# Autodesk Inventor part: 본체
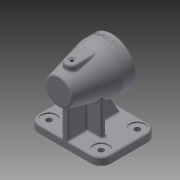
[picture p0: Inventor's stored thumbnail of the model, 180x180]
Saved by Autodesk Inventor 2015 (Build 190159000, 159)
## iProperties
Created: 2024-12
Part Number: 본체
Material: 일반
Document SubType Name: Modeling
Designer: 10401
Density: 1 g/cm^3
Appearance: 기본값
Author: 10401
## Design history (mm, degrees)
sketch "스케치1"
  geometry: L1 (-57, 44.5)-(57, 44.5); L2 (57, 44.5)-(57, -44.5); L3 (57, -44.5)-(-57, -44.5); L4 (-57, -44.5)-(-57, 44.5); L5 (-57, 44.5)-(57, -44.5); L6 (57, 44.5)-(-57, -44.5); 1 further point
  constraints: 12 end point, 2 midpoint, 2 parallel, 1 horizontal, 1 perpendicular
  dimensions: "d0" = 114 distance of L1.start L1.end; "d1" = 89 distance of L1.end L2.end
extrude "돌출1" new body sketch "스케치1" distance "d2" = 12; taper "d3" = 0 deg
fillet "모깎기1" dims "d4" = 16
sketch "스케치2"
  geometry: A1 r 16 centre (-41, 28.5) between (-41, 44.5) and (-57, 28.5) reference; A2 r 16 centre (-41, -28.5) between (-57, -28.5) and (-41, -44.5) reference; A3 r 16 centre (41, -28.5) between (41, -44.5) and (57, -28.5) reference; A4 r 16 centre (41, 28.5) between (57, 28.5) and (41, 44.5) reference; 1 further point
hole "구멍1" sketch "스케치2" at (41, 28.5), (41, -28.5), (-41, -28.5), (-41, 28.5) diameter "d5" = 9; stored, may be unused: countersink angle "d9" = 90 deg, drill point angle "d11" = 118 deg; dims "d6" = 6, "d7" = 24, "d8" = 2, "d10" = 8
sketch "스케치3"
  geometry: L1 (-41, -44.5)-(41, -44.5) reference; L2 (41, 44.5)-(-41, 44.5) reference; L3 (-5, 44.5)-(5, 44.5); L4 (5, 44.5)-(5, -37.5); L5 (5, -37.5)-(-5, -37.5); L6 (-5, -37.5)-(-5, 44.5); L7 (0, 0)-(0, 13.919)
  constraints: 10 end point, 2 parallel, 1 horizontal, 1 perpendicular, 1 point on line, 1 vertical, 1 other
  dimensions: "d13" = 10 distance of L4.end L5.end; "d14" = 7 distance between parallel lines of L1 L5
extrude "돌출2" join sketch "스케치3" distance "d15" = 70; taper "d16" = 0 deg
sketch "스케치4"
  geometry: L1 (-5, 44.5)-(-41, 44.5) reference; L2 (-28, 15.5)-(28, 15.5); L3 (28, 15.5)-(28, 7.5); L4 (28, 7.5)-(-28, 7.5); L5 (-28, 7.5)-(-28, 15.5); L6 (0, 0)-(0, 11.5)
  constraints: 10 end point, 2 parallel, 1 horizontal, 1 perpendicular, 1 vertical, 1 other
  dimensions: "d17" = 56 distance of L2.start L2.end; "d18" = 8 distance of L2.end L3.end; "d19" = 29 distance between parallel lines of L2 L1
extrude "돌출3" join sketch "스케치4" distance "d20" = 70; taper "d21" = 0 deg
feature "면 기울기1" dims angle "d22" = 30 deg
sketch "스케치5"
  geometry: L1 (54.5, 82)-(54.5, 103); L2 (-9.5, 119)-(-29.5, 119); L3 (-29.5, 119)-(-29.5, 82); L4 (-29.5, 82)-(54.5, 82); L5 (28.5, 0)-(-28.5, 0) reference; L6 (-44.5, 12)-(-44.5, 0) reference; L7 (54.5, 103)-(-9.5, 119); 1 further point
  constraints: 10 end point, 2 perpendicular, 1 vertical
  dimensions: "d23" = 20 distance of L2.start L2.end; "d24" = 119 distance between parallel lines of L5 L2; "d25" = 82 distance between parallel lines of L5 L4; "d28" = 21 distance of L1.start L1.end; "d29" = 15 distance between parallel lines of L6 L3; "d30" = 99 distance between parallel lines of L1 L6
revolve "회전1" sketch "스케치5" stored, may be unused: angle "d32" = 90 deg
sketch "스케치7"
  geometry: C1 r 37 at (0, 0) reference; C2 r 23.5 at (0, 0); 1 further point
  constraints: 1 centre point, 1 coincident
  dimensions: "d36" = 47 diameter of C2
extrude "돌출5" cut sketch "스케치7" distance "d37" = 18; taper "d38" = 0 deg
sketch "스케치8"
  geometry: L1 (54.5, 61)-(44.5, 58.5) reference; L2 (44.5, 58.5)-(44.5, 0) reference; L3 (44.5, 0)-(-44.5, 0) reference; L4 (-44.5, 0)-(-44.5, 12) reference; L5 (-44.5, 12)-(-37.5, 12) reference; L6 (-37.5, 12)-(-18.447, 45) reference; L7 (-18.447, 45)-(-29.5, 45) reference; L8 (-29.5, 45)-(-29.5, 58.5) reference; L9 (-29.5, 58.5)-(-11.5, 58.5) reference; L10 (-11.5, 58.5)-(-11.5, 105.5) reference; L11 (-11.5, 105.5)-(-29.5, 105.5) reference; L12 (-29.5, 105.5)-(-29.5, 119) reference; L13 (-29.5, 119)-(-9.5, 119) reference; L14 (-9.5, 119)-(54.5, 103) reference; L15 (54.5, 103)-(54.5, 61) reference; L16 (33.5, 103.096)-(-11.5, 114.346); L17 (-11.5, 114.346)-(-11.5, 105.5); L18 (-11.5, 82)-(33.5, 82); L19 (33.5, 82)-(33.5, 103.096); 1 further point
  constraints: 8 end point, 1 horizontal, 1 midpoint, 1 parallel, 1 perpendicular, 1 vertical
  dimensions: "d39" = 5 distance between parallel lines of L16 L14; "d40" = 45 horizontal distance of L16.end L16.start
revolve "회전2" sketch "스케치8" stored, may be unused: angle "d41" = 90 deg
sketch "스케치9"
  geometry: C1 r 21.096 at (0, 0) reference; C2 r 17.5 at (0, 0); 1 further point
  constraints: 1 centre point, 1 coincident
  dimensions: "d42" = 35 diameter of C2
extrude "돌출6" cut sketch "스케치9" distance "d43" = 10; taper "d44" = 0 deg
sketch "스케치10"
  geometry: C1 r 17.5 at (0, 0) reference; C2 r 15.5 at (0, 0); 1 further point
  constraints: 1 centre point, 1 coincident
  dimensions: "d45" = 31 diameter of C2
extrude "돌출7" cut sketch "스케치10" distance "d46" = 3; taper "d47" = 0 deg
fillet "모깎기3" dims "d48" = 3
fillet "모깎기4" dims "d49" = 0.3
fillet "모깎기5" dims "d50" = 3
chamfer "모따기1" distance "d51" = 1; stored, may be unused: second distance "d52" = 2, angle "d53" = 45 deg
fillet "모깎기6" dims "d54" = 5
chamfer "모따기2" distance "d55" = 1; stored, may be unused: second distance "d56" = 2, angle "d57" = 45 deg
fillet "모깎기7" dims "d58" = 3
fillet "모깎기9" dims "d68" = 3
fillet "모깎기10" dims "d69" = 3
fillet "모깎기11" dims "d70" = 3
sketch "스케치16"
  geometry: C1 r 37 at (0, 0) reference; 2 further points
  constraints: 1 vertical alignment
  dimensions: "d78" = 28.5 distance of C1.centre point (0, 28.5)
hole "구멍2" sketch "스케치16" at (0, 28.5) diameter "d79" = 3.242; stored, may be unused: countersink angle "d83" = 90 deg, drill point angle "d85" = 118 deg; dims "d80" = 8, "d81" = 4, "d82" = 2, "d84" = 10
node "작업 평면2"
sketch "스케치18"
  geometry: L1 (16.733, -9.869)-(16.733, -29.5) reference; L2 (16.733, -29.5)-(-16.733, -29.5) reference; L3 (-16.733, -29.5)-(-16.733, -9.869) reference; L4 (10, 33.5)-(10, 0.572); L5 (-10, 33.5)-(-10, 0.572); A1 r 10 centre (0, 33.5) between (10, 33.5) and (-10, 33.5); 3 further points
  constraints: 4 end point, 2 perpendicular, 2 point on circle, 1 centre point, 5 other
  dimensions: "d92" = 20 diameter of A1
extrude "돌출10" join sketch "스케치18" stored distance "d93" = 20; taper "d94" = 0 deg
fillet "모깎기12" dims "d95" = 3
sketch "스케치19"
  geometry: A1 r 7 centre (0, 33.5) between (7, 33.5) and (-7, 33.5) reference; 1 further point
hole "구멍3" sketch "스케치19" at (0, 33.5) diameter "d96" = 5.188; stored, may be unused: countersink angle "d100" = 90 deg, drill point angle "d102" = 118 deg; dims "d97" = 12, "d98" = 10, "d99" = 1, "d101" = 20
node "작업 평면3"
sketch "스케치20"
  geometry: L1 (37, -29.5)-(-37, -29.5) reference; 2 further points
  constraints: 1 vertical alignment, 1 other
  dimensions: "d104" = 9 distance from line of L1 point (0, -20.5)
feature "엠보싱2" sketch "스케치20" dims "d0" = 114, "d1" = 89, "d105" = 0.5, "d106" = 0
node "솔리드1"
pattern_circular "원형 패턴1" dims angle "d87" = 360 deg
node "절단 모서리 투영1"
node "절단 모서리 투영3"
other parameters: "d91" = -115, "d103" = -119
